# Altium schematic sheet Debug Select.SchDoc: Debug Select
size A3; CompanyName: Hitex GmbH; Address1: Greschbachstr. 12; Address2: 76229 Karlsruhe, Germany; Address3: www.hitex.com; DocumentNumber: 7; SheetNumber: 7; SheetTotal: 8; PageSetup: Record=PageOptions¦CenterHorizontal=True¦CenterVertical=True¦PrintScale=1.04¦XCorrection=1.00¦YCorrection=1.00¦PrintKind=0¦BorderSize=5000000¦LeftOffset=0¦BottomOffset=0¦Orientation=2¦PaperLength=1000¦PaperWidth=1000¦Scale=100¦PaperSource=7¦PrintQuality=1200¦MediaType=1¦DitherType=10¦PaperKind=A3¦PrintScaleMode=1
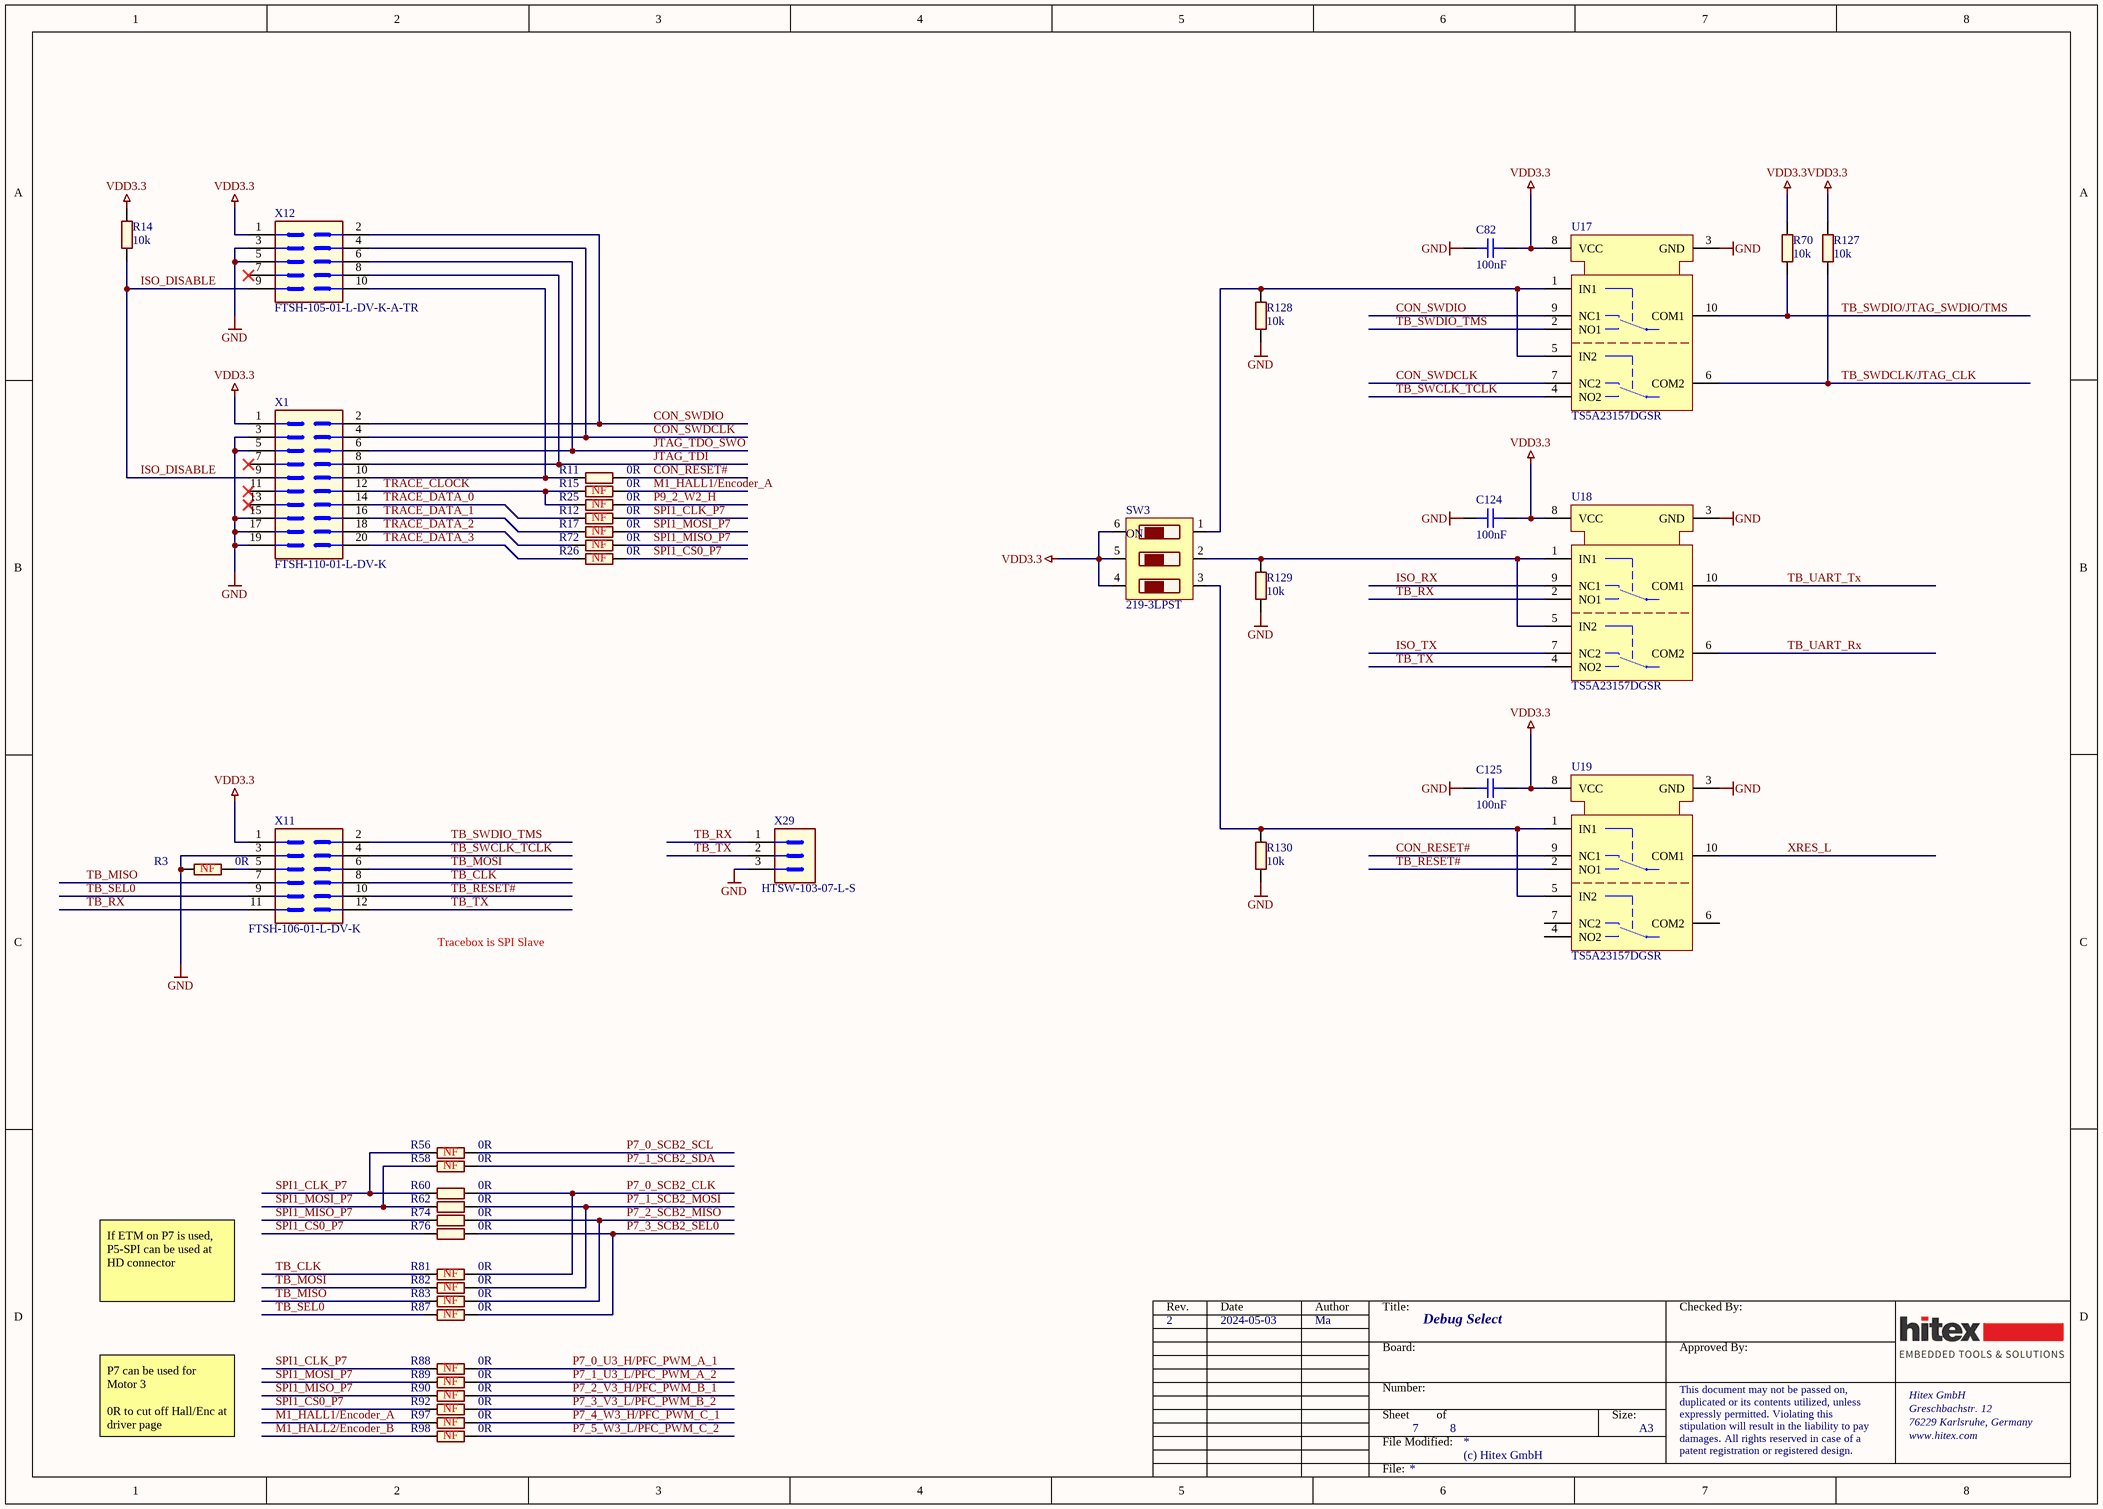
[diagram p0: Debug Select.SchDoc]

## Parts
C82  100nF  [CAPC1005X55N-0]
C124  100nF  [CAPC1005X55N-0]
C125  100nF  [CAPC1005X55N-0]
R3  0R  [RESC1005X03N]
R11  0R  [RESC1005X03N]
R12  0R  [RESC1005X03N]
R14  10k  [RESC1005X40N]
R15  0R  [RESC1005X03N]
R17  0R  [RESC1005X03N]
R25  0R  [RESC1005X03N]
R26  0R  [RESC1005X03N]
R56  0R  [RESC1005X03N]
R58  0R  [RESC1005X03N]
R60  0R  [RESC1005X03N]
R62  0R  [RESC1005X03N]
R70  10k  [RESC1005X40N]
R72  0R  [RESC1005X03N]
R74  0R  [RESC1005X03N]
R76  0R  [RESC1005X03N]
R81  0R  [RESC1005X03N]
R82  0R  [RESC1005X03N]
R83  0R  [RESC1005X03N]
R87  0R  [RESC1005X03N]
R88  0R  [RESC1005X03N]
R89  0R  [RESC1005X03N]
R90  0R  [RESC1005X03N]
R92  0R  [RESC1005X03N]
R97  0R  [RESC1005X03N]
R98  0R  [RESC1005X03N]
R127  10k  [RESC1005X40N]
R128  10k  [RESC1005X40N]
R129  10k  [RESC1005X40N]
R130  10k  [RESC1005X40N]
SW3  219-3LPST  [219-3LP]
U17  TS5A23157DGSR  [VSSOP50P490X110-10N]
U18  TS5A23157DGSR  [VSSOP50P490X110-10N]
U19  TS5A23157DGSR  [VSSOP50P490X110-10N]
X1  FTSH-110-01-L-DV-K  [CON-M-SMD-FTSH-110-01-L-DV-K]
X11  FTSH-106-01-L-DV-K  [CON-M-SMD-FTSH-106-01-L-DV-K]
X12  FTSH-105-01-L-DV-K-A-TR  [CON-M-SMD-FTSH-105-01-L-DV-K-A-TR]
X29  HTSW-103-07-L-S  [CON-M-THT-HTSW-103-07-L-S]

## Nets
GND: C82.1 C124.1 C125.1 R3.2 R128.1 R129.1 R130.1 U17.3(GND) U18.3(GND) U19.3(GND) X1.3 X1.5 X1.15 X1.17 X1.19 X11.3 X12.3 X12.5 X29.3
VDD3.3: C82.2 C124.2 C125.2 R14.2 R70.2 R127.2 SW3.4 SW3.5 SW3.6 U17.8(VCC) U18.8(VCC) U19.8(VCC) X1.1 X11.1 X12.1
CON_RESET#: R11.1 U19.9(NC1)
CON_SWDCLK: U17.7(NC2) X1.4 X12.4
CON_SWDIO: U17.9(NC1) X1.2 X12.2
ISO_DISABLE: R14.1 X1.9 X12.9
ISO_RX: U18.9(NC1)
ISO_TX: U18.7(NC2)
JTAG_TDI: X1.8 X12.8
JTAG_TDO_SWO: X1.6 X12.6
M1_HALL1/Encoder_A: R15.1 R97.2
M1_HALL2/Encoder_B: R98.2
P7_0_SCB2_CLK: R60.1 R81.1
P7_0_SCB2_SCL: R56.1
P7_0_U3_H/PFC_PWM_A_1: R88.1
P7_1_SCB2_MOSI: R62.1 R82.1
P7_1_SCB2_SDA: R58.1
P7_1_U3_L/PFC_PWM_A_2: R89.1
P7_2_SCB2_MISO: R74.1 R83.1
P7_2_V3_H/PFC_PWM_B_1: R90.1
P7_3_SCB2_SEL0: R76.1 R87.1
P7_3_V3_L/PFC_PWM_B_2: R92.1
P7_4_W3_H/PFC_PWM_C_1: R97.1
P7_5_W3_L/PFC_PWM_C_2: R98.1
P9_2_W2_H: R25.1
SPI1_CLK_P7: R12.1 R56.2 R60.2 R88.2
SPI1_CS0_P7: R26.1 R76.2 R92.2
SPI1_MISO_P7: R72.1 R74.2 R90.2
SPI1_MOSI_P7: R17.1 R58.2 R62.2 R89.2
TB_CLK: R81.2 X11.8
TB_MISO: R83.2 X11.7
TB_MOSI: R82.2 X11.6
TB_RESET#: U19.2(NO1) X11.10
TB_RX: U18.2(NO1) X11.11 X29.1
TB_SEL0: R87.2 X11.9
TB_SWCLK_TCLK: U17.4(NO2) X11.4
TB_SWDCLK/JTAG_CLK: R127.1 U17.6(COM2)
TB_SWDIO/JTAG_SWDIO/TMS: R70.1 U17.10(COM1)
TB_SWDIO_TMS: U17.2(NO1) X11.2
TB_TX: U18.4(NO2) X11.12 X29.2
TB_UART_Rx: U18.6(COM2)
TB_UART_Tx: U18.10(COM1)
TRACE_CLOCK: R15.2 R25.2 X1.12
TRACE_DATA_0: R12.2 X1.14
TRACE_DATA_1: R17.2 X1.16
TRACE_DATA_2: R72.2 X1.18
TRACE_DATA_3: R26.2 X1.20
XRES_L: U19.10(COM1)
NetR3_1: R3.1 X11.5
NetR11_2: R11.2 X1.10 X12.10
NetR128_2: R128.2 SW3.1 U17.1(IN1) U17.5(IN2)
NetR129_2: R129.2 SW3.2 U18.1(IN1) U18.5(IN2)
NetR130_2: R130.2 SW3.3 U19.1(IN1) U19.5(IN2)

Not connected (* = marked no-connect by the designer): U19 4(NO2) 6(COM2) 7(NC2); X1 7* 11* 13*; X12 7*

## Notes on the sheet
- (near R25) NF
- (near R15) NF
- (near R12) NF
- (near R17) NF
- (near R72) NF
- (near R26) NF
- (near R3) NF
- Tracebox is SPI Slave
- (near R56) NF
- (near R58) NF
- If ETM on P7 is used, P5-SPI can be used at HD connector
- (near R81) NF
- (near R82) NF
- (near R83) NF
- (near R87) NF
- 2
- 2024-05-03
- Ma
- (near R88) NF
- (near R89) NF
- (near R90) NF
- P7 can be used for
  Motor 3
  0R to cut off Hall/Enc at driver page
- (near R92) NF
- (near R97) NF
- (near R98) NF

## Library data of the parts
C82 C124 C125 = 310625: CAP / CERA / 100nF / 50V / 10% / X7R (EIA) / -55°C to 125°C / 0402(1005) / SMD / -; Multiple Parts: No; Legacy PartNumber: CAP01010920; Manufacturer: MuRata; Manufacturer Order Number: GRM155R71H104KE14D; Symbol Type: Capacitor; Single; Standard; 2 Pins; Alternate View: Yes; Article Number: 310625; Version Number: V01; Combined Parameters: TC:X7R (EIA);Tol.:-10%/+10%;Vdc:50V; QuickPick: 100nF / 50V / 10% / X7R (EIA) / 0402 (1005M); Type: Standard; Style: Single; Package Metric: 1005; Package Imperial: 0402; ComponentStatus: Released; PLMStatus: Active; HTX: 01.22.0596.0
R3 R11 R12 R15 R17 R25 R26 R56 R58 R60 R62 R72 R74 R76 R81-R83 R87-R90 R92 R97 R98 = 327372: RES / STD / 0R / 63mW / 0R / 0ppm/K / -55°C to 155°C / 0402(1005) / SMD / -; Multiple Parts: No; Legacy PartNumber: RES00000001; Manufacturer: Yageo; Manufacturer Order Number: RC0402JR-070RL; Symbol Type: Resistor; Single; Standard; 2 Pins; Alternate View: Yes; Article Number: 327372; Version Number: V01; Combined Parameters: TCR:0ppm/K;Tol.:-0R/+0R;Vdc:50V;Idc:1A;P:63mW; QuickPick: 0R / 0R / 0.063 / 0402 (1005); Style: Single; Package Metric: 1005; Package Imperial: 0402; ComponentStatus: Released; PLMStatus: Active; Voltage DC (max): 50V; HTX: 01.02.0902.0
R14 R70 R127-R130 = 342167: RES / STD / 10k / 63mW / 1% / 100ppm/K / -55°C to 155°C / 0402(1005) / SMD / -; Multiple Parts: No; Legacy PartNumber: RES01800457; Manufacturer: Vishay; Manufacturer Order Number: CRCW040210K0FK; Symbol Type: Resistor; Single; Standard; 2 Pins; Alternate View: Yes; Article Number: 342167; Version Number: V01; Combined Parameters: TCR:100ppm/K;Tol.:-1%/+1%;Vdc:50V;Idc:-;P:63mW; QuickPick: 10k / 1% / 0.063 / 0402 (1005); Style: Single; Automotive Qualified: AEC Q200; Package Metric: 1005; Package Imperial: 0402; ComponentStatus: Released; PLMStatus: Active; Voltage DC (max): 50V; HTX: 01.02.0703.0
SW3 = DIPSW-3: RM2.54, 3polig, SMD, ON-Position; Manufacturer: CTS; Designer: Th; CheckOrientation: true; HTX: 03.00.0012.0
U17-U19 = TS5A23157DGSR: TS5A23157DGSR, 1.8V-5V, 2:1 (SPDT), 2-channel analog switch, 10R; PartNumber: 00.30.0133.0; Manufacturer: Texas Instruments; Designer: Th; CheckOrientation: true
X1 = 387533: SMT Micro Header, 1.27mm Pitch, 20 pins, Vertical, Double Row, Keying Shroud; Legacy PartNumber: CON01501020; Manufacturer: Samtec; Article Number: 387533; Version Number: V01; Legacy DeviceID: SAM_FTSH-110-01-L-DV-K; Combined Parameters: Board-to-Board Header (male);10x2;Mounting:SMT;Orient:0° (vertical);Shielded:No; QuickPick: 0° (vertical) / Board-to-Board; Style: Strip; Automotive Qualified: No; ComponentStatus: Released; PLMStatus: Active; Second Source allowed: Yes; Voltage DC (max): na; HTX: 03.13.0129.0
X11 = 638279: Connector Header Surface Mount 12 position 0.050 (1.27mm); Manufacturer: Samtec; Article Number: 638279; Version Number: V01; Legacy DeviceID: SAM_FTSH-106-01-L-DV-K; Combined Parameters: Board-to-Board Header (male);2x6;Mounting:SMT;Orient:0° (vertical);Shielded:No; QuickPick: 0° (vertical) / Board-to-Board; Automotive Qualified: No; ComponentStatus: Released; PLMStatus: Active; Second Source allowed: Yes; Voltage DC (max): na; HTX: 03.13.0536.0
X12 = 382494: SMT Micro Header, 1.27mm pitch, 10 pin, Vertical, Double Row, Keying Shroud with Alignment pin, DAP; Manufacturer: Samtec; Article Number: 382494; Version Number: V01; Legacy DeviceID: SAM_FTSH-105-01-L-DV-K-A-TR; Combined Parameters: Board-to-Board Header (male);5x2;Mounting:SMT;Orient:0° (vertical);Shielded:-; QuickPick: 0° (vertical) / Board-to-Board; Style: Strip; Automotive Qualified: No; ComponentStatus: Released; PLMStatus: Active; Second Source allowed: Yes; Voltage DC (max): na; HTX: 03.13.0132.0
X29 = 378477: Through hole .025 SQ Post Header, 2.54mm pitch, 3 pin, vertical, single row; Legacy PartNumber: CON01500137; Manufacturer: Samtec; Article Number: 378477; Version Number: V01; Legacy DeviceID: SAM_HTSW-103-07-L-S; Combined Parameters: Board-to-Board Header (male);3x1;Mounting:THT;Orient:0° (vertical);Shielded:No; QuickPick: 0° (vertical) / Board-to-Board; Style: Strip; Automotive Qualified: No; ComponentStatus: Released; PLMStatus: Active; Second Source allowed: Yes; Voltage DC (max): na; HTX: 03.20.0002.0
